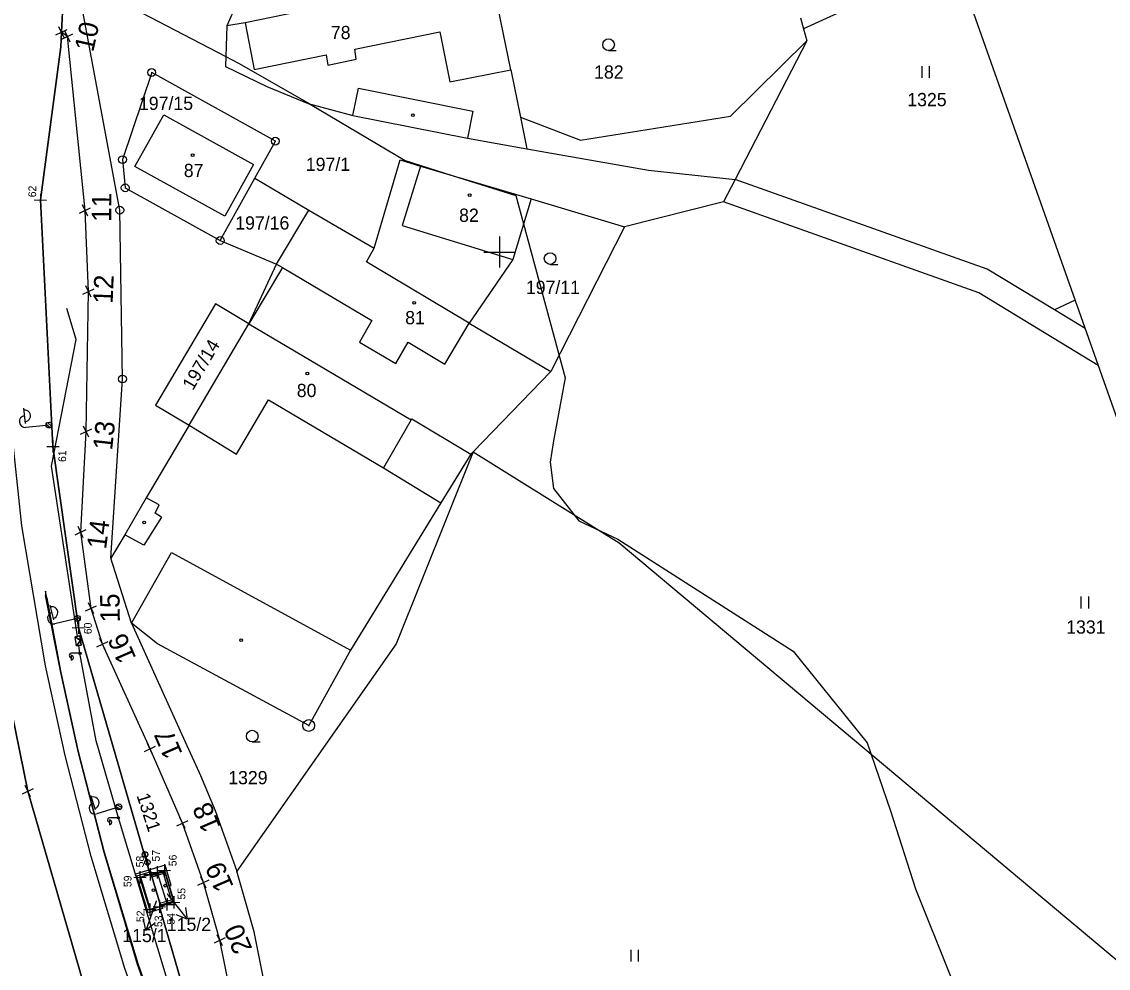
# Model space of a CAD drawing. Extents: x -779950 to -779537, y -1100753 to -1100261.
# Drawn here: x -779761.4 to -779621.8, y -1100492 to -1100370.4 of the extents above; entities that cross this region are included whole.
import ezdxf

# ---------------------------------------------------------------- set-up
doc = ezdxf.new("R2010")
doc.units = 0
for name, color, linetype in [('BPEJ', 7, 'Continuous'), ('GD_Demolice', 7, 'Continuous'), ('GD_Nový stav', 7, 'Continuous'), ('GD_Starý stav', 7, 'Continuous'), ('Groma (60)', 7, 'Continuous'), ('Katastr_HRANICE DRÁHY', 7, 'Continuous'), ('Katastr_Hranice parcel', 7, 'Continuous'), ('Katastr_Parcelní čísla', 7, 'Continuous'), ('Katastr_Slučkované čáry', 7, 'Continuous'), ('Katastr_Značky kultur', 7, 'Continuous'), ('čtvercová síť', 7, 'Continuous')]:
    doc.layers.add(name, color=color, linetype=linetype)

# ---------------------------------------------------------------- blocks, each defined once
blk = doc.blocks.new('POINT_DISPLAY')
for p, q in [((-0.56, -0.56), (0.56, 0.56)), ((-0.56, 0.56), (0.56, -0.56))]:
    blk.add_line(p, q)
blk = doc.blocks.new('C691')
at = {"layer": 'čtvercová síť'}
for p, q in [((0, 0.5), (0, -0.5)), ((-0.5, 0), (0.5, 0))]:
    blk.add_line(p, q, dxfattribs=at)

msp = doc.modelspace()

# ---------------------------------------------------------------- linework, layer by layer
at = {"layer": 'BPEJ'}
for points in [[(-779625.47, -1100688.02), (-779650.47, -1100650.42), (-779681.32, -1100605.77), (-779703.57, -1100572.42), (-779721.36, -1100542.95), (-779739.67, -1100497.93), (-779743.7, -1100484.06), (-779744.94, -1100484.43), (-779746.21, -1100480.3), (-779744.9, -1100479.92), (-779754.11, -1100448.23), (-779757.39, -1100424.96), (-779758.99, -1100393.31), (-779756.39, -1100373.64), (-779756.29, -1100371.78), (-779755.9, -1100364.14)], [(-779755.75, -1100364.13), (-779735.18, -1100374.9), (-779733.56, -1100375.75), (-779724.75, -1100380.75), (-779724.32, -1100381.01), (-779712.13, -1100388.25), (-779706.09, -1100390.16), (-779697.88, -1100392.75), (-779691.56, -1100416.13), (-779693.06, -1100424.25), (-779693.5, -1100427), (-779693.06, -1100430.38), (-779689.81, -1100434.5), (-779684.81, -1100436.88), (-779662.25, -1100451.25), (-779652.75, -1100463), (-779649.75, -1100471.75), (-779646.56, -1100481.75), (-779642.06, -1100493), (-779636.88, -1100504.88), (-779632.38, -1100516.13), (-779623.63, -1100538.75), (-779616.56, -1100561.88), (-779608.63, -1100582.25)], [(-779705.21, -1100593.05), (-779732.47, -1100545.72), (-779746.3, -1100518.64), (-779760.6, -1100469.23), (-779766.2, -1100441.87), (-779773.7, -1100397.5), (-779773.71, -1100397.46), (-779790.89, -1100392.34), (-779799.56, -1100395.07), (-779805.37, -1100396.9), (-779815.24, -1100406.16), (-779820.13, -1100410.74), (-779826.84, -1100421.48), (-779831.96, -1100434.79), (-779833.08, -1100437.69), (-779834.29, -1100440.83), (-779835.16, -1100450.08), (-779835.88, -1100457.88), (-779832.63, -1100489.75), (-779832.41, -1100502.43), (-779832.37, -1100504.43), (-779837.25, -1100541.25), (-779840.13, -1100556.13), (-779842.69, -1100593.88)]]:
    msp.add_lwpolyline(points, dxfattribs=at)
at = {"layer": 'Defpoints'}
msp.add_line((-779537.42, -1100656.91), (-779677.36, -1100260.91), dxfattribs=at)
at = {"layer": 'GD_Demolice'}
for p, q in [((-779760.93, -1100422), (-779761.13, -1100420.06)), ((-779758.27, -1100422.25), (-779760.87, -1100422.52)), ((-779757.74, -1100422.55), (-779758.26, -1100422.14)), ((-779757.55, -1100422.35), (-779758.1, -1100421.9)), ((-779757.28, -1100447.23), (-779757.74, -1100445.34)), ((-779753.88, -1100447.14), (-779754.49, -1100446.76)), ((-779754.61, -1100447.13), (-779757.15, -1100447.74)), ((-779754.05, -1100447.36), (-779754.61, -1100447.02)), ((-779751.92, -1100471.64), (-779752.5, -1100469.78)), ((-779749.26, -1100471.36), (-779751.76, -1100472.14)), ((-779748.68, -1100471.56), (-779749.27, -1100471.26)), ((-779748.53, -1100471.33), (-779749.17, -1100470.99))]:
    msp.add_line(p, q, dxfattribs=at)
msp.add_lwpolyline([(-779746.1, -1100480.29), (-779743.04, -1100479.39), (-779741.8, -1100483.47), (-779744.86, -1100484.41), (-779746.1, -1100480.29)], dxfattribs=at)
for centre in [(-779757.89, -1100422.21), (-779757.89, -1100422.21), (-779754.24, -1100447.04), (-779754.24, -1100447.04), (-779748.9, -1100471.25), (-779748.9, -1100471.25)]:
    msp.add_circle(centre, 0.375, dxfattribs=at)
for centre, start, end in [((-779761.02, -1100421.03), 275.2338, 96.6389), ((-779760.95, -1100421.77), 95.9364, 275.9364), ((-779757.33, -1100447.02), 103.6332, 283.6332), ((-779757.5, -1100446.29), 282.9306, 104.3358), ((-779752.2, -1100470.71), 286.6292, 108.0344), ((-779751.99, -1100471.43), 107.3318, 287.3318)]:
    msp.add_arc(centre, 0.75, start, end, dxfattribs=at)
at = {"layer": 'GD_Nový stav'}
for p, q in [((-779753.85, -1100449.9), (-779754.54, -1100449.39)), ((-779754.36, -1100450.58), (-779753.85, -1100449.9)), ((-779753.91, -1100451.52), (-779754.06, -1100450.53)), ((-779754.05, -1100451.52), (-779755.03, -1100451.52)), ((-779755.03, -1100451.72), (-779755.03, -1100452.45)), ((-779753.87, -1100451.39), (-779754.04, -1100451.56)), ((-779753.79, -1100451.46), (-779753.98, -1100451.65)), ((-779751.83, -1100462.75), (-779753.91, -1100451.52)), ((-779748.98, -1100472.65), (-779751.83, -1100462.75)), ((-779749.12, -1100472.65), (-779750.1, -1100472.65)), ((-779750.1, -1100472.85), (-779750.1, -1100473.58)), ((-779748.93, -1100472.52), (-779749.11, -1100472.69)), ((-779748.85, -1100472.59), (-779749.04, -1100472.78)), ((-779742.71, -1100493.43), (-779748.98, -1100472.65)), ((-779743.56, -1100483.86), (-779744.73, -1100480.04)), ((-779743.63, -1100483.62), (-779744.65, -1100480.28))]:
    msp.add_line(p, q, dxfattribs=at)
for points in [[(-779754.24, -1100449.35), (-779757.57, -1100427.51), (-779754.39, -1100411.21), (-779755.59, -1100407.24)], [(-779753.94, -1100449.3), (-779754.54, -1100449.39), (-779753.85, -1100449.9), (-779753.94, -1100449.3)], [(-779753.85, -1100449.9), (-779754.36, -1100450.58), (-779753.76, -1100450.49), (-779753.85, -1100449.9)], [(-779742.42, -1100481.43), (-779742.18, -1100481.36), (-779742.98, -1100478.72), (-779746.79, -1100479.88)]]:
    msp.add_lwpolyline(points, dxfattribs=at)
for points in [[(-779754.54, -1100449.39), (-779753.94, -1100449.3), (-779753.76, -1100450.49), (-779754.36, -1100450.58)], [(-779745.61, -1100476.97), (-779745.71, -1100477), (-779745.17, -1100478.74), (-779745.08, -1100478.71)], [(-779743.32, -1100484.31), (-779745.13, -1100484.87), (-779746.59, -1100480.08), (-779744.78, -1100479.53), (-779744.63, -1100480.01), (-779744.73, -1100480.04), (-779743.56, -1100483.86), (-779743.46, -1100483.83)], [(-779743.56, -1100483.86), (-779741.84, -1100483.34), (-779743, -1100479.51), (-779744.73, -1100480.04)], [(-779742.15, -1100483.17), (-779743.17, -1100479.82), (-779744.65, -1100480.28), (-779744.73, -1100480.04), (-779743, -1100479.51), (-779741.84, -1100483.34), (-779743.56, -1100483.86), (-779743.63, -1100483.62)]]:
    msp.add_lwpolyline(points, close=True, dxfattribs=at)
for centre, radius in [((-779753.91, -1100451.52), 0.141), ((-779753.91, -1100451.52), 0.141), ((-779748.98, -1100472.65), 0.141), ((-779748.98, -1100472.65), 0.141), ((-779745.55, -1100477.35), 0.35), ((-779745.24, -1100478.36), 0.35)]:
    msp.add_circle(centre, radius, dxfattribs=at)
for centre, start, end in [((-779755.03, -1100451.8), 89.9837, 269.9837), ((-779755.03, -1100452.09), 269.2811, 90.6862), ((-779750.1, -1100472.94), 89.9837, 269.9837), ((-779750.1, -1100473.22), 269.2811, 90.6862)]:
    msp.add_arc(centre, 0.281, start, end, dxfattribs=at)
at = {"layer": 'GD_Starý stav'}
for points in [[(-779725.52, -1100545.61), (-779736.06, -1100523.7), (-779741.09, -1100511.62), (-779748.13, -1100491.99), (-779752.47, -1100477.63), (-779755.8, -1100464.65), (-779758.32, -1100453.12), (-779761.4, -1100435.15), (-779764.27, -1100408.44)], [(-779758.15, -1100444.4), (-779758.34, -1100443.55), (-779758.34, -1100444.12)], [(-779735.27, -1100521.25), (-779739.52, -1100511), (-779746.5, -1100491.5), (-779750.82, -1100477.09), (-779754.15, -1100464.15), (-779756.35, -1100454.01), (-779758.34, -1100444.12)], [(-779758.15, -1100444.4), (-779756.35, -1100454), (-779754.13, -1100464.12), (-779750.8, -1100477.04), (-779746.45, -1100491.5), (-779739.48, -1100510.95), (-779735.36, -1100520.89)]]:
    msp.add_lwpolyline(points, dxfattribs=at)
at = {"layer": 'Katastr_HRANICE DRÁHY'}
for points in [[(-779755.85, -1100363.13), (-779756.29, -1100371.78)], [(-779755.53, -1100372.32), (-779756.29, -1100371.78)], [(-779753.26, -1100394.66), (-779755.53, -1100372.32)], [(-779752.82, -1100405.06), (-779753.26, -1100394.66)], [(-779753.12, -1100423.05), (-779752.82, -1100405.06)], [(-779753.82, -1100435.97), (-779753.12, -1100423.05)], [(-779752.49, -1100445.75), (-779753.82, -1100435.97)], [(-779766.2, -1100441.87), (-779760.6, -1100469.23)], [(-779751.01, -1100450.35), (-779752.49, -1100445.75)], [(-779744.91, -1100463.81), (-779751.01, -1100450.35)], [(-779740.73, -1100473.32), (-779744.91, -1100463.81)], [(-779760.6, -1100469.23), (-779746.3, -1100518.64)], [(-779738.03, -1100480.96), (-779740.73, -1100473.32)], [(-779735.92, -1100488.37), (-779738.03, -1100480.96)], [(-779733.71, -1100499.34), (-779735.92, -1100488.37)]]:
    msp.add_lwpolyline(points, dxfattribs=at)
at = {"layer": 'Katastr_Hranice parcel'}
for p, q in [((-779744.69, -1100376.94), (-779748.44, -1100388.13)), ((-779728.8, -1100385.76), (-779744.69, -1100376.94)), ((-779731.44, -1100390.52), (-779728.8, -1100385.76)), ((-779748.44, -1100388.13), (-779748.1, -1100391.75)), ((-779735.89, -1100398.52), (-779731.44, -1100390.52)), ((-779731.44, -1100390.52), (-779724.49, -1100394.6)), ((-779748.1, -1100391.75), (-779735.89, -1100398.52)), ((-779735.89, -1100398.52), (-779728.64, -1100401.54)), ((-779703.39, -1100425.66), (-779684.62, -1100437.35)), ((-779684.62, -1100437.35), (-779650.39, -1100466.03)), ((-779650.39, -1100466.03), (-779599.22, -1100508.89))]:
    msp.add_line(p, q, dxfattribs=at)
for points in [[(-779641.48, -1100362.43), (-779660.95, -1100371.32)], [(-779748.79, -1100394.62), (-779754.54, -1100363.74)], [(-779701.1, -1100364.07), (-779732.67, -1100370.55)], [(-779698.54, -1100376.59), (-779701.1, -1100364.07)], [(-779732.89, -1100366.08), (-779735.04, -1100370.94)], [(-779661.32, -1100369.94), (-779660.95, -1100371.32)], [(-779735.04, -1100370.94), (-779735.22, -1100376.15)], [(-779732.67, -1100370.55), (-779735.04, -1100370.94)], [(-779660.95, -1100371.32), (-779660.52, -1100372.89)], [(-779756.29, -1100371.78), (-779756.39, -1100373.64)], [(-779756.39, -1100373.64), (-779758.99, -1100393.31)], [(-779670.32, -1100382.55), (-779660.52, -1100372.89)], [(-779660.52, -1100372.89), (-779669.73, -1100390.67)], [(-779735.22, -1100376.15), (-779729.9, -1100378.73)], [(-779698.54, -1100376.59), (-779697.31, -1100382.69)], [(-779729.9, -1100378.73), (-779724.57, -1100380.94)], [(-779724.57, -1100380.94), (-779718.84, -1100382.47)], [(-779746.87, -1100389), (-779743.13, -1100382.38)], [(-779743.13, -1100382.38), (-779731.61, -1100388.77)], [(-779718.84, -1100382.47), (-779704.11, -1100385.38)], [(-779689.58, -1100385.63), (-779670.32, -1100382.55)], [(-779697.31, -1100382.69), (-779696.49, -1100386.73)], [(-779697.31, -1100382.69), (-779689.58, -1100385.63)], [(-779704.11, -1100385.38), (-779696.49, -1100386.73)], [(-779716.12, -1100399.52), (-779712.76, -1100388.14)], [(-779712.76, -1100388.14), (-779710.13, -1100388.96)], [(-779735.31, -1100395.41), (-779746.87, -1100389)], [(-779731.61, -1100388.77), (-779735.31, -1100395.41)], [(-779710.13, -1100388.96), (-779695.94, -1100393.16)], [(-779669.73, -1100390.67), (-779671.21, -1100393.54)], [(-779637.32, -1100402.21), (-779669.73, -1100390.67)], [(-779758.99, -1100393.31), (-779757.39, -1100424.96)], [(-779695.94, -1100393.16), (-779698.27, -1100400.96)], [(-779695.94, -1100393.16), (-779683.92, -1100396.77)], [(-779671.21, -1100393.54), (-779683.92, -1100396.77)], [(-779638.4, -1100405.22), (-779671.21, -1100393.54)], [(-779748.45, -1100416.31), (-779748.79, -1100394.62)], [(-779728.64, -1100401.54), (-779724.49, -1100394.6)], [(-779724.49, -1100394.6), (-779716.12, -1100399.52)], [(-779683.92, -1100396.77), (-779693.39, -1100415.33)], [(-779717.08, -1100401.27), (-779716.12, -1100399.52)], [(-779732.19, -1100409.21), (-779728.64, -1100401.54)], [(-779716.54, -1100401.59), (-779717.08, -1100401.27)], [(-779703.9, -1100409.15), (-779716.54, -1100401.59)], [(-779698.27, -1100400.96), (-779703.9, -1100409.15)], [(-779628.68, -1100407.4), (-779637.32, -1100402.21)], [(-779623.05, -1100414.57), (-779638.4, -1100405.22)], [(-779626.02, -1100406.18), (-779628.68, -1100407.4)], [(-779736.5, -1100406.66), (-779744.2, -1100419.68)], [(-779732.19, -1100409.21), (-779736.5, -1100406.66)], [(-779624.74, -1100409.8), (-779628.68, -1100407.4)], [(-779703.9, -1100409.15), (-779693.39, -1100415.33)], [(-779739.89, -1100422.23), (-779732.19, -1100409.21)], [(-779732.19, -1100409.21), (-779711.34, -1100421.54)], [(-779693.39, -1100415.33), (-779703.39, -1100425.66)], [(-779749.94, -1100439.32), (-779748.45, -1100416.31)], [(-779744.2, -1100419.68), (-779739.89, -1100422.23)], [(-779711.34, -1100421.54), (-779711.26, -1100421.4)], [(-779711.26, -1100421.4), (-779703.67, -1100425.94)], [(-779739.89, -1100422.23), (-779745.39, -1100431.58)], [(-779757.39, -1100424.96), (-779754.11, -1100448.23)], [(-779703.39, -1100425.66), (-779713.28, -1100450.31)], [(-779703.39, -1100425.66), (-779703.67, -1100425.94)], [(-779703.67, -1100425.94), (-779707.54, -1100432.2)], [(-779745.39, -1100431.58), (-779748.16, -1100436.29)], [(-779707.54, -1100432.2), (-779719.16, -1100451.11)], [(-779748.16, -1100436.29), (-779749.94, -1100439.32)], [(-779747.29, -1100447.66), (-779749.94, -1100439.32)], [(-779754.11, -1100448.23), (-779744.9, -1100479.92)], [(-779747.29, -1100447.66), (-779740.81, -1100461.95)], [(-779743.94, -1100450.29), (-779747.29, -1100447.66)], [(-779724.52, -1100460.8), (-779743.94, -1100450.29)], [(-779713.28, -1100450.31), (-779733.77, -1100479.51)], [(-779719.16, -1100451.11), (-779724.52, -1100460.8)], [(-779740.81, -1100461.95), (-779738.43, -1100467.21)], [(-779738.43, -1100467.21), (-779736.53, -1100471.69)], [(-779736.53, -1100471.69), (-779733.77, -1100479.51)], [(-779744.9, -1100479.92), (-779746.21, -1100480.3)], [(-779746.21, -1100480.3), (-779744.94, -1100484.43)], [(-779744.9, -1100479.92), (-779743.98, -1100479.65)], [(-779743.98, -1100479.65), (-779743.07, -1100479.39)], [(-779743.98, -1100479.65), (-779742.72, -1100483.77)], [(-779743.07, -1100479.39), (-779741.85, -1100483.51)], [(-779731.54, -1100487.31), (-779733.77, -1100479.51)], [(-779744.94, -1100484.43), (-779743.7, -1100484.06)], [(-779742.72, -1100483.77), (-779743.7, -1100484.06)], [(-779743.7, -1100484.06), (-779739.67, -1100497.93)], [(-779741.85, -1100483.51), (-779742.72, -1100483.77)], [(-779729.3, -1100498.46), (-779731.54, -1100487.31)]]:
    msp.add_lwpolyline(points, dxfattribs=at)
at = {"layer": 'Katastr_Parcelní čísla'}
for p, q in [((-779742.72, -1100482.38), (-779742.61, -1100482.53)), ((-779744.12, -1100483.33), (-779744.14, -1100483.36)), ((-779740.35, -1100484.18), (-779740.13, -1100485.67)), ((-779744.31, -1100486.16), (-779745.44, -1100487.14))]:
    msp.add_line(p, q, dxfattribs=at)
for points in [[(-779742.61, -1100482.53), (-779740.13, -1100485.67), (-779741.53, -1100485.11)], [(-779744.14, -1100483.36), (-779745.44, -1100487.14), (-779745.73, -1100485.67)]]:
    msp.add_lwpolyline(points, dxfattribs=at)
at = {"layer": 'Katastr_Slučkované čáry'}
for points in [[(-779732.67, -1100370.55), (-779731.54, -1100376.57)], [(-779718.59, -1100373.94), (-779707.65, -1100371.72)], [(-779707.65, -1100371.72), (-779706.37, -1100378.13)], [(-779718.42, -1100375.25), (-779718.59, -1100373.94)], [(-779731.54, -1100376.57), (-779722.29, -1100374.69)], [(-779722.29, -1100374.69), (-779722.06, -1100376)], [(-779722.06, -1100376), (-779718.42, -1100375.25)], [(-779706.37, -1100378.13), (-779698.54, -1100376.59)], [(-779718.84, -1100382.47), (-779718.1, -1100378.97)], [(-779718.1, -1100378.97), (-779703.41, -1100381.91)], [(-779703.41, -1100381.91), (-779704.11, -1100385.38)], [(-779696.49, -1100386.73), (-779680.84, -1100389.5)], [(-779710.13, -1100388.96), (-779712.5, -1100396.59)], [(-779680.84, -1100389.5), (-779669.73, -1100390.67)], [(-779712.5, -1100396.59), (-779698.27, -1100400.96)], [(-779727.9, -1100401.98), (-779732.19, -1100409.21)], [(-779728.64, -1100401.54), (-779727.9, -1100401.98)], [(-779727.9, -1100401.98), (-779716.4, -1100408.79), (-779717.99, -1100411.58), (-779713.32, -1100414.31)], [(-779707.01, -1100414.39), (-779703.9, -1100409.15)], [(-779713.32, -1100414.31), (-779711.73, -1100411.58)], [(-779711.73, -1100411.58), (-779707.01, -1100414.39)], [(-779733.8, -1100425.94), (-779729.68, -1100418.97)], [(-779729.68, -1100418.97), (-779714.9, -1100427.7)], [(-779711.34, -1100421.54), (-779714.9, -1100427.7)], [(-779739.89, -1100422.23), (-779733.8, -1100425.94)], [(-779714.9, -1100427.7), (-779707.54, -1100432.2)], [(-779743.74, -1100432.44), (-779745.39, -1100431.58)], [(-779744.25, -1100433.54), (-779743.74, -1100432.44)], [(-779743.45, -1100434.04), (-779745.69, -1100437.63)], [(-779743.45, -1100434.04), (-779744.25, -1100433.54)], [(-779745.69, -1100437.63), (-779748.16, -1100436.29)], [(-779747.29, -1100447.66), (-779742.16, -1100438.6)], [(-779742.16, -1100438.6), (-779719.16, -1100451.11)]]:
    msp.add_lwpolyline(points, dxfattribs=at)
at = {"layer": 'Katastr_Značky kultur'}
for p, q in [((-779685.99, -1100374.12), (-779684.99, -1100374.12)), ((-779744.74, -1100376.94), (-779744.64, -1100376.94)), ((-779645.73, -1100376.11), (-779645.73, -1100377.61)), ((-779644.73, -1100377.61), (-779644.73, -1100376.11)), ((-779728.85, -1100385.76), (-779728.75, -1100385.76)), ((-779748.49, -1100388.13), (-779748.39, -1100388.13)), ((-779748.15, -1100391.75), (-779748.05, -1100391.75)), ((-779748.84, -1100394.62), (-779748.74, -1100394.62)), ((-779735.94, -1100398.52), (-779735.84, -1100398.52)), ((-779693.49, -1100401.58), (-779692.49, -1100401.58)), ((-779748.5, -1100416.31), (-779748.4, -1100416.31)), ((-779625.29, -1100444.25), (-779625.29, -1100445.75)), ((-779624.29, -1100445.75), (-779624.29, -1100444.25)), ((-779724.57, -1100460.8), (-779724.47, -1100460.8)), ((-779731.77, -1100462.91), (-779730.77, -1100462.91)), ((-779683.14, -1100489.59), (-779683.14, -1100491.09)), ((-779682.14, -1100491.09), (-779682.14, -1100489.59))]:
    msp.add_line(p, q, dxfattribs=at)
for centre, radius in [((-779685.99, -1100373.37), 0.75), ((-779744.69, -1100376.94), 0.499), ((-779711.14, -1100382.41), 0.175), ((-779728.8, -1100385.76), 0.499), ((-779748.44, -1100388.13), 0.499), ((-779739.43, -1100387.56), 0.175), ((-779748.1, -1100391.75), 0.499), ((-779703.83, -1100392.7), 0.175), ((-779748.79, -1100394.62), 0.499), ((-779735.89, -1100398.52), 0.499), ((-779693.49, -1100400.83), 0.75), ((-779710.95, -1100406.53), 0.175), ((-779748.45, -1100416.31), 0.499), ((-779724.69, -1100415.59), 0.175), ((-779745.65, -1100434.72), 0.175), ((-779733.18, -1100449.84), 0.175), ((-779724.52, -1100460.8), 0.756), ((-779731.77, -1100462.16), 0.75), ((-779744.45, -1100481.94), 0.175), ((-779742.95, -1100481.36), 0.175)]:
    msp.add_circle(centre, radius, dxfattribs=at)

# ---------------------------------------------------------------- block references
at = {"layer": 'Groma (60)'}
for p, rotation in [((-779756.29, -1100371.78), 70.53751088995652), ((-779755.53, -1100372.32), 70.53751088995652), ((-779758.99, -1100393.31), -45.71641134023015), ((-779753.26, -1100394.66), 70.53751088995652), ((-779752.82, -1100405.06), 70.53751088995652), ((-779753.12, -1100423.05), 70.53751088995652), ((-779757.39, -1100424.96), -45.71641134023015), ((-779753.82, -1100435.97), 70.53751088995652), ((-779752.49, -1100445.75), 70.53751088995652), ((-779754.11, -1100448.23), -45.71641134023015), ((-779751.01, -1100450.35), 70.53751088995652), ((-779744.91, -1100463.81), 70.53751088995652), ((-779760.6, -1100469.23), 70.53751088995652), ((-779740.73, -1100473.32), 70.53751088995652), ((-779743.98, -1100479.65), -45.71641134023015), ((-779743.07, -1100479.39), -45.71641134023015), ((-779746.21, -1100480.3), -45.71641134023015), ((-779744.9, -1100479.92), -45.71641134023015), ((-779738.03, -1100480.96), 70.53751088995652), ((-779742.72, -1100483.77), -45.71641134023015), ((-779741.85, -1100483.51), -45.71641134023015), ((-779744.94, -1100484.43), -45.71641134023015), ((-779743.7, -1100484.06), -45.71641134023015), ((-779735.92, -1100488.37), 70.53751088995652)]:
    msp.add_blockref('POINT_DISPLAY', p, dxfattribs=dict(at, rotation=rotation))
at = {"layer": 'čtvercová síť', "xscale": 4, "yscale": 4}
msp.add_blockref('C691', (-779700, -1100400), dxfattribs=at)

# ---------------------------------------------------------------- texts
at = {"layer": 'Groma (60)'}
for s, height, rotation, p in [('10', 2.5, 77.3575, (-779752.22, -1100374.4)), ('62', 1, 89.0486, (-779759.55, -1100392.97)), ('11', 2.5, 89.6936, (-779749.9, -1100396.12)), ('12', 2.5, 87.6258, (-779749.72, -1100406.68)), ('13', 2.5, 83.6487, (-779749.79, -1100425.53)), ('61', 1, 89.0486, (-779755.7, -1100426.96)), ('14', 2.5, 82.8174, (-779750.56, -1100438.24)), ('15', 2.5, 90.7763, (-779748.78, -1100447.55)), ('60', 1, 89.0486, (-779752.41, -1100449.07)), ('16', 2.5, 113.3411, (-779746.65, -1100452.13)), ('17', 2.5, 113.3411, (-779740.69, -1100464.39)), ('18', 2.5, 113.3411, (-779735.77, -1100473.83)), ('57', 1, 89.0486, (-779743.66, -1100478.27)), ('56', 1, 89.0486, (-779741.51, -1100478.87)), ('58', 1, 89.0486, (-779745.71, -1100479.02)), ('19', 2.5, 113.3411, (-779734.12, -1100481.46)), ('59', 1, 89.0486, (-779747.3, -1100481.56)), ('55', 1, 89.0486, (-779740.38, -1100483.15)), ('52', 1, 89.0486, (-779745.65, -1100486.05)), ('53', 1, 89.0486, (-779743.34, -1100486.69)), ('54', 1, 89.0486, (-779741.74, -1100486.37)), ('20', 2.5, 113.3411, (-779731.72, -1100489.45))]:
    msp.add_text(s, height=height, rotation=rotation, dxfattribs=at).set_placement(p)
at = {"layer": 'Katastr_Parcelní čísla'}
for s, p in [('78', (-779721.67, -1100372.66)), ('182', (-779687.84, -1100377.73)), ('1325', (-779647.6, -1100381.27)), ('197/15', (-779746.33, -1100381.75)), ('197/1', (-779724.89, -1100389.58)), ('87', (-779740.57, -1100390.37)), ('82', (-779705.19, -1100396.12)), ('197/16', (-779733.96, -1100397.11)), ('197/11', (-779696.61, -1100405.38)), ('81', (-779712.12, -1100409.27)), ('80', (-779726.05, -1100418.62)), ('1331', (-779627.18, -1100449)), ('1329', (-779734.86, -1100468.34)), ('115/2', (-779742.75, -1100487.18)), ('115/1', (-779748.47, -1100488.61))]:
    msp.add_text(s, height=1.7, dxfattribs=at).set_placement(p)
for s, rotation, p in [('197/14', 59.4, (-779739.4, -1100417.86)), ('1321', 288, (-779746.66, -1100469.78))]:
    msp.add_text(s, height=1.7, rotation=rotation, dxfattribs=at).set_placement(p)

doc.saveas('drawing.dxf')
